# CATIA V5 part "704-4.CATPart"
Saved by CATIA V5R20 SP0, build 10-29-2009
Part number: 704-4
Revision: TUTTO
Definition: NON CONOSCIUTO
Nomenclature: 704-4
Source: Unknown
Bounding box of the stored display mesh (mm): x -45 to 10, y -10 to 10, z 0 to 95
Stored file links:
  C:\Users\Utente\Desktop\IO LAVORO\3D X SITO CF\X SITO\704\704-4.CATPart
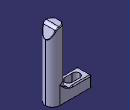
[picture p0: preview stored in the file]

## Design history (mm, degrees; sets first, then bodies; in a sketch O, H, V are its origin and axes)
Body1 "Importato1" (main body)
  Solid1: solid without history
